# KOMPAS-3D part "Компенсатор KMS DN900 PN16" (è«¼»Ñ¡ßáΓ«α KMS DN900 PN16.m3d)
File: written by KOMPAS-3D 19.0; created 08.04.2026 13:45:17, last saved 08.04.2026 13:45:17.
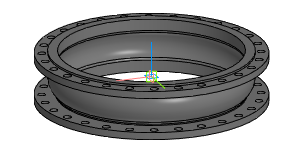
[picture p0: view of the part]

Document properties: Автор: Энергия; Полное имя файла: Z:\3.Личные\kachalov\3d для проектировщиков\7.1 Компенсатор\stp_Компенсатор KSM\Компенсатор KMS DN900 PN16.m3d

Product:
- Part/product: Компенсатор KMS DN900 PN16

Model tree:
1. Операция без истории:1  (labels: Компенсатор KMS DN900 PN16)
